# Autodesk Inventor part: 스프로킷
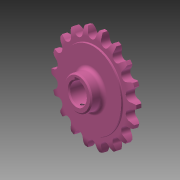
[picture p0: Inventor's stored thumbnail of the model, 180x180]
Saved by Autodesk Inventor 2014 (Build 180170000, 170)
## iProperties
Created: 2016-03
Part Number: 스프로킷
Material: 강철, 탄소
Document SubType Name: Modeling
Designer: mduedu
Density: 7.87 g/cm^3
Mass: 301.818 g
Surface Area: 124.882 cm^2
Volume: 38.3505 cm^3
Appearance: 분홍색
Author: mduedu
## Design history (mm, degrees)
sketch "스케치1"
  geometry: L1 (0, 5)-(29.5, 5); L2 (29.5, 5)-(29.5, 4.1); L3 (30, 3.6)-(33.625, 3.6); L4 (40, 2)-(40, 0); L5 (40, 0)-(0, 0); L6 (0, 0)-(0, 5); L7 (0, -5)-(29.5, -5); L8 (29.5, -5)-(29.5, -4.1); L9 (30, -3.6)-(33.625, -3.6); L10 (40, -2)-(40, 0); L11 (0, 0)-(0, -5); A1 r 13.5 centre (33.625, -9.9) between (40, 2) and (33.625, 3.6); A2 r 13.5 centre (33.625, 9.9) between (33.625, -3.6) and (40, -2); A3 r 0.5 centre (30, 4.1) between (29.5, 4.1) and (30, 3.6); A4 r 0.5 centre (30, -4.1) between (30, -3.6) and (29.5, -4.1); 2 further points
  constraints: 22 end point, 8 point on circle, 6 symmetric about line, 5 tangent, 4 centre point, 4 parallel, 4 point on line, 1 equal radius, 1 horizontal, 1 perpendicular, 1 other
  dimensions: "d0" = 80 diameter of L4 L6; "d2" = 59 diameter of L2 L6; "d3" = 1.6 vertical distance of L4.start L3.end; "d4" = 3.6 distance from line of L4.end L3; "d5" = 5 distance between parallel lines of L5 L1; "d6" = 13.5 radius of A1; "d15" = 0.5 radius of A3
revolve "회전1" sketch "스케치1" stored, may be unused: angle "d7" = 90 deg
sketch "스케치2" dims "d8" = 65.2, "d11" = 80
  geometry: L1 (0, 0)-(0, 32.6); A1 r 36.57 centre (0, 0) between (-16.231, 32.771) and (0, 36.57); A2 r 3.97 centre (0, 36.57) between (-3.866, 35.665) and (0, 32.6); A3 r 12.7 centre (-16.231, 32.771) between (-3.866, 35.665) and (-5.534, 39.615); A4 r 12.7 centre (16.231, 32.771) between (5.534, 39.615) and (3.866, 35.665); A5 r 3.97 centre (0, 36.57) between (0, 32.6) and (3.866, 35.665); A6 r 40 centre (0, 0) between (5.534, 39.615) and (-5.534, 39.615); 2 further points
  constraints: 12 point on circle, 6 centre point, 4 coincident, 3 symmetric about line, 2 end point, 1 point on line, 1 tangent, 1 vertical, 1 vertical alignment, 7 other
  dimensions: "d10" = 73.14 diameter of A1; "d12" = 12.7 radius of A3
extrude "돌출1" cut sketch "스케치2" stored distance "d13" = 10; taper "d14" = 0 deg
sketch "스케치3"
  geometry: C1 r 13 at (0, 0); 1 further point
  constraints: 1 centre point, 1 coincident
  dimensions: "d19" = 26 diameter of C1
extrude "돌출2" join sketch "스케치3" distance "d20" = 10; taper "d21" = 0 deg
fillet "모깎기1" dims "d22" = 3
sketch "스케치4"
  geometry: L1 (-2.5, 0)-(2.5, 0); L2 (2.5, 0)-(2.5, 10.3); L3 (2.5, 10.3)-(-2.5, 10.3); L4 (-2.5, 10.3)-(-2.5, 0); C1 r 8 at (0, 0); 2 further points
  constraints: 8 end point, 2 coincident, 2 parallel, 1 centre point, 1 horizontal, 1 midpoint, 1 perpendicular
  dimensions: "d23" = 16 diameter of C1; "d25" = 5 distance of L2.end L3.end; "d26" = 10.3 distance of L1.end L2.end
extrude "돌출3" cut sketch "스케치4" stored distance "d27" = 8; taper "d28" = 0 deg
chamfer "모따기2" distance "d42" = 1; stored, may be unused: second distance "d43" = 2, angle "d44" = 45 deg
node "작업 평면2"
sketch "스케치6"
  geometry: L1 (-12, 15)-(12, 15) reference; 2 further points
  constraints: 1 vertical alignment
  dimensions: "d59" = 4 distance from line of point (0.008, 11) L1
hole "구멍2" sketch "스케치6" at (0.008, 11) diameter "d48" = 3; stored, may be unused: countersink angle "d52" = 90 deg, drill point angle "d54" = 118 deg; dims "d49" = 6, "d50" = 4, "d51" = 2, "d53" = 8
thread "Thread1" dims "d56" = 10, "d57" = 0
node "솔리드1"
pattern_circular "원형 패턴1" dims angle "d17" = 360 deg
other parameters: "d55" = -13
